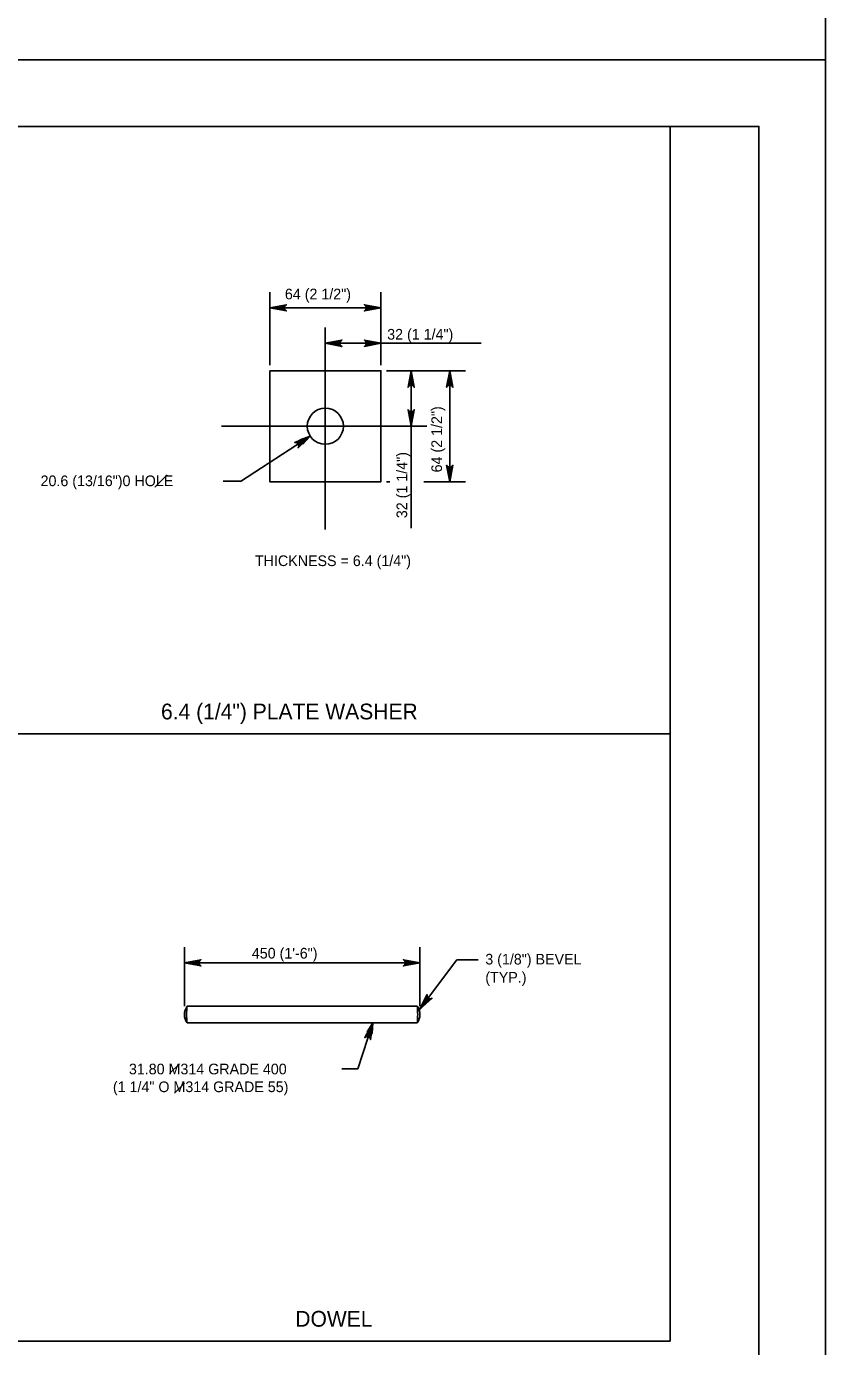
# Model space of a CAD drawing. Extents: x 0 to 36.3, y -66 to 0.
# Drawn here: x 25.01 to 34, y -58.48 to -43.62 of the extents above; entities that cross this region are included whole.
import ezdxf

# ---------------------------------------------------------------- set-up
doc = ezdxf.new("R2010")
doc.units = 0
for name, color, linetype in [('1', 7, 'Continuous'), ('3', 7, 'Continuous'), ('4', 7, 'Continuous'), ('5', 7, 'Continuous'), ('62', 7, 'Continuous'), ('63', 7, 'Continuous')]:
    doc.layers.add(name, color=color, linetype=linetype)

msp = doc.modelspace()

# ---------------------------------------------------------------- linework, layer by layer
at = {"layer": '1'}
msp.add_lwpolyline([(1.75, -65.25), (33.25, -65.25), (33.25, -44.75), (1.75, -44.75)], close=True, dxfattribs=at)
at = {"layer": '3'}
for p, q in [((32.25, -58.417), (32.25, -44.75)), ((27.746, -47.438), (27.746, -46.614)), ((28.996, -47.438), (28.996, -46.614)), ((28.996, -46.792), (27.746, -46.792)), ((28.371, -49.284), (28.371, -47.012)), ((28.996, -47.438), (28.996, -47.012)), ((28.371, -47.19), (30.123, -47.19)), ((29.058, -47.499), (29.948, -47.499)), ((29.058, -47.499), (29.514, -47.499)), ((29.337, -49.27), (29.337, -47.499)), ((29.771, -48.749), (29.771, -47.499)), ((27.201, -48.124), (29.514, -48.124)), ((26.451, -48.81), (26.59, -48.67)), ((27.423, -48.742), (27.222, -48.742)), ((29.058, -48.749), (29.097, -48.749)), ((29.481, -48.749), (29.948, -48.749)), ((1.75, -51.583), (32.25, -51.583)), ((26.786, -54.647), (26.786, -53.984)), ((29.435, -54.647), (29.435, -53.984)), ((26.786, -54.161), (29.435, -54.161)), ((28.735, -55.353), (28.556, -55.353)), ((1.75, -58.417), (32.25, -58.417))]:
    msp.add_line(p, q, dxfattribs=at)
for points in [[(27.746, -46.792), (27.933, -46.757), (27.918, -46.767), (27.911, -46.779), (27.909, -46.792), (27.911, -46.804), (27.918, -46.817), (27.933, -46.826), (27.746, -46.792), (27.918, -46.817), (27.911, -46.804), (27.746, -46.792), (27.909, -46.792), (27.911, -46.779), (27.746, -46.792), (27.918, -46.767)], [(28.996, -46.792), (28.81, -46.826), (28.824, -46.817), (28.831, -46.804), (28.834, -46.792), (28.831, -46.779), (28.824, -46.767), (28.81, -46.757), (28.996, -46.792), (28.824, -46.767), (28.831, -46.779), (28.996, -46.792), (28.834, -46.792), (28.831, -46.804), (28.996, -46.792), (28.824, -46.817)], [(28.371, -47.19), (28.558, -47.155), (28.543, -47.165), (28.536, -47.177), (28.534, -47.19), (28.536, -47.202), (28.543, -47.215), (28.558, -47.225), (28.371, -47.19), (28.543, -47.215), (28.536, -47.202), (28.371, -47.19), (28.534, -47.19), (28.536, -47.177), (28.371, -47.19), (28.543, -47.165)], [(28.996, -47.19), (28.81, -47.225), (28.824, -47.215), (28.831, -47.202), (28.834, -47.19), (28.831, -47.177), (28.824, -47.165), (28.81, -47.155), (28.996, -47.19), (28.824, -47.165), (28.831, -47.177), (28.996, -47.19), (28.834, -47.19), (28.831, -47.202), (28.996, -47.19), (28.824, -47.215)], [(29.337, -47.499), (29.372, -47.686), (29.362, -47.671), (29.349, -47.664), (29.337, -47.662), (29.324, -47.664), (29.312, -47.671), (29.302, -47.686), (29.337, -47.499), (29.312, -47.671), (29.324, -47.664), (29.337, -47.499), (29.337, -47.662), (29.349, -47.664), (29.337, -47.499), (29.362, -47.671)], [(29.771, -47.499), (29.806, -47.686), (29.796, -47.671), (29.784, -47.664), (29.771, -47.662), (29.759, -47.664), (29.746, -47.671), (29.736, -47.686), (29.771, -47.499), (29.746, -47.671), (29.759, -47.664), (29.771, -47.499), (29.771, -47.662), (29.784, -47.664), (29.771, -47.499), (29.796, -47.671)], [(29.337, -48.124), (29.302, -47.938), (29.312, -47.952), (29.324, -47.96), (29.337, -47.962), (29.349, -47.96), (29.362, -47.952), (29.372, -47.938), (29.337, -48.124), (29.362, -47.952), (29.349, -47.96), (29.337, -48.124), (29.337, -47.962), (29.324, -47.96), (29.337, -48.124), (29.312, -47.952)], [(28.201, -48.236), (27.418, -48.746)], [(28.201, -48.236), (28.064, -48.366), (28.071, -48.35), (28.07, -48.336), (28.065, -48.324), (28.056, -48.315), (28.043, -48.308), (28.026, -48.308), (28.201, -48.236), (28.043, -48.308), (28.056, -48.315), (28.201, -48.236), (28.065, -48.324), (28.07, -48.336), (28.201, -48.236), (28.071, -48.35)], [(29.771, -48.749), (29.736, -48.563), (29.746, -48.577), (29.759, -48.585), (29.771, -48.587), (29.784, -48.585), (29.796, -48.577), (29.806, -48.563), (29.771, -48.749), (29.796, -48.577), (29.784, -48.585), (29.771, -48.749), (29.771, -48.587), (29.759, -48.585), (29.771, -48.749), (29.746, -48.577)], [(26.786, -54.161), (26.972, -54.126), (26.958, -54.136), (26.95, -54.149), (26.948, -54.161), (26.95, -54.174), (26.958, -54.186), (26.972, -54.196), (26.786, -54.161), (26.958, -54.186), (26.95, -54.174), (26.786, -54.161), (26.948, -54.161), (26.95, -54.149), (26.786, -54.161), (26.958, -54.136)], [(29.435, -54.161), (29.249, -54.196), (29.263, -54.186), (29.27, -54.174), (29.273, -54.161), (29.27, -54.149), (29.263, -54.136), (29.249, -54.126), (29.435, -54.161), (29.263, -54.136), (29.27, -54.149), (29.435, -54.161), (29.273, -54.161), (29.27, -54.174), (29.435, -54.161), (29.263, -54.186)], [(28.907, -54.837), (28.735, -55.353)], [(28.907, -54.837), (28.881, -55.024), (28.877, -55.008), (28.867, -54.997), (28.856, -54.991), (28.843, -54.989), (28.829, -54.992), (28.815, -55.002), (28.907, -54.837), (28.829, -54.992), (28.843, -54.989), (28.907, -54.837), (28.856, -54.991), (28.867, -54.997), (28.907, -54.837), (28.877, -55.008)]]:
    msp.add_lwpolyline(points, dxfattribs=at)
for points in [[(27.864, -46.772), (27.864, -46.811), (27.746, -46.792)], [(28.878, -46.772), (28.878, -46.811), (28.996, -46.792)], [(28.489, -47.17), (28.489, -47.209), (28.371, -47.19)], [(28.878, -47.17), (28.878, -47.209), (28.996, -47.19)], [(27.746, -47.499), (27.746, -48.749), (28.996, -48.749), (28.996, -47.499)], [(29.317, -47.617), (29.356, -47.617), (29.337, -47.499)], [(29.751, -47.617), (29.791, -47.617), (29.771, -47.499)], [(29.317, -48.006), (29.356, -48.006), (29.337, -48.124)], [(28.201, -48.236), (28.086, -48.275), (28.118, -48.325)], [(29.751, -48.631), (29.791, -48.631), (29.771, -48.749)], [(26.904, -54.142), (26.904, -54.181), (26.786, -54.161)], [(29.317, -54.142), (29.317, -54.181), (29.435, -54.161)], [(28.907, -54.837), (28.842, -54.939), (28.898, -54.958)]]:
    msp.add_lwpolyline(points, close=True, dxfattribs=at)
msp.add_circle((28.371, -48.124), 0.203, dxfattribs=at)
at = {"layer": '4'}
for p, q in [((26.816, -54.649), (29.404, -54.649)), ((26.815, -54.837), (29.405, -54.837))]:
    msp.add_line(p, q, dxfattribs=at)
for points in [[(29.432, -54.688), (29.851, -54.128), (30.092, -54.128)], [(29.432, -54.688), (29.516, -54.518), (29.515, -54.535), (29.521, -54.548), (29.53, -54.558), (29.541, -54.563), (29.555, -54.565), (29.572, -54.56), (29.432, -54.688), (29.555, -54.565), (29.541, -54.563), (29.432, -54.688), (29.53, -54.558), (29.521, -54.548), (29.432, -54.688), (29.515, -54.535)]]:
    msp.add_lwpolyline(points, dxfattribs=at)
msp.add_lwpolyline([(29.432, -54.688), (29.436, -54.685), (29.434, -54.683)], close=True, dxfattribs=at)
for centre, radius, start, end in [((26.946, -54.744), 0.16, 143.8823, 215.4749), ((27.573, -54.747), 0.763, 172.631, 186.7262), ((29.275, -54.744), 0.16, 324.5251, 36.1177), ((28.647, -54.747), 0.763, 353.2738, 7.369)]:
    msp.add_arc(centre, radius, start, end, dxfattribs=at)
at = {"layer": '5'}
for p, q in [((26.617, -55.408), (26.729, -55.296)), ((26.674, -55.627), (26.786, -55.515))]:
    msp.add_line(p, q, dxfattribs=at)
at = {"layer": '62'}
msp.add_line((34, -44), (34, -44), dxfattribs=at)
at = {"layer": '63'}
for points in [[(0, -44), (34, -44), (34, -22), (0, -22)], [(0, -66), (34, -66), (34, -44), (0, -44)]]:
    msp.add_lwpolyline(points, close=True, dxfattribs=at)

# ---------------------------------------------------------------- texts
at = {"layer": '3'}
for s, height, p in [('64 (2 1/2")', 0.12, (27.916, -46.696)), ('32 (1 1/4")', 0.12, (29.067, -47.149)), ('20.6 (13/16")0 HOLE', 0.12, (25.167, -48.798)), ('THICKNESS = 6.4 (1/4")', 0.12, (27.579, -49.697)), ('6.4 (1/4") PLATE WASHER', 0.17717, (26.522, -51.422)), ('450 (1\'-6")', 0.12, (27.544, -54.113)), ('3 (1/8") BEVEL', 0.12, (30.171, -54.18)), ('(TYP.)', 0.12, (30.171, -54.384)), ('31.80 M314 GRADE 400', 0.12, (26.161, -55.416)), ('(1 1/4" O M314 GRADE 55)', 0.12, (25.981, -55.616)), ('DOWEL', 0.1772, (28.033, -58.255))]:
    msp.add_text(s, height=height, dxfattribs=at).set_placement(p)
for s, p in [('64 (2 1/2")', (29.684, -48.643)), ('32 (1 1/4")', (29.292, -49.158))]:
    msp.add_text(s, height=0.12, rotation=90, dxfattribs=at).set_placement(p)

doc.saveas('drawing.dxf')
